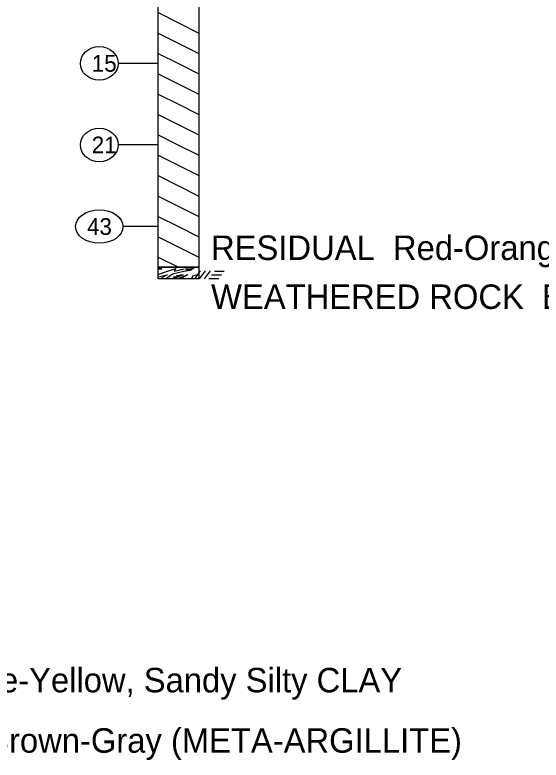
# Model space of a CAD drawing. Extents: x -26 to 303, y -74 to 518.
# Drawn here: x 158.98 to 191.22, y -74.2 to -28.53 of the extents above; entities that cross this region are included whole.
import ezdxf

# ---------------------------------------------------------------- set-up
doc = ezdxf.new("R2010")
doc.units = 0
for name, color, linetype in [('Prop Road Sect_ Boring - Material (Desc Tx)', 7, 'Continuous'), ('Prop Road Sect_ Boring - Material (Outline)', 7, 'Continuous'), ('Prop Road Sect_ Boring - Peripheral (HR Indicator)', 7, 'Continuous'), ('Prop Road Sect_ Boring - Peripheral (SPT Oval + Leader)', 7, 'Continuous'), ('Prop Road Sect_ Boring - Peripheral (SPT Tx)', 7, 'Continuous')]:
    doc.layers.add(name, color=color, linetype=linetype)

msp = doc.modelspace()

# ---------------------------------------------------------------- linework, layer by layer
at = {"layer": 'Prop Road Sect_ Boring - Material (Outline)'}
for p, q in [((167.75, -28.391), (168.999, -29.015)), ((167.75, -28.391), (168.999, -29.015)), ((168.999, -29.015), (170.248, -29.639)), ((168.999, -29.015), (170.248, -29.639)), ((167.75, -29.639), (170.248, -30.888)), ((167.75, -29.639), (170.248, -30.888)), ((167.75, -29.639), (170.248, -30.888)), ((167.75, -29.639), (170.248, -30.888)), ((170.248, -29.639), (170.25, -29.641)), ((170.248, -29.639), (170.25, -29.641)), ((170.248, -29.639), (170.25, -29.641)), ((170.248, -29.639), (170.25, -29.641)), ((167.75, -30.888), (168.999, -31.512)), ((167.75, -30.888), (168.999, -31.512)), ((170.248, -30.888), (170.25, -30.889)), ((170.248, -30.888), (170.25, -30.889)), ((168.999, -31.512), (170.248, -32.137)), ((168.999, -31.512), (170.248, -32.137)), ((167.75, -32.137), (170.248, -33.386)), ((167.75, -32.137), (170.248, -33.386)), ((167.75, -32.137), (170.248, -33.386)), ((167.75, -32.137), (170.248, -33.386)), ((170.248, -32.137), (170.25, -32.138)), ((170.248, -32.137), (170.25, -32.138)), ((170.248, -32.137), (170.25, -32.138)), ((170.248, -32.137), (170.25, -32.138)), ((167.75, -33.386), (168.999, -34.01)), ((167.75, -33.386), (168.999, -34.01)), ((170.248, -33.386), (170.25, -33.387)), ((170.248, -33.386), (170.25, -33.387)), ((168.999, -34.01), (170.248, -34.634)), ((168.999, -34.01), (170.248, -34.634)), ((167.75, -34.634), (170.248, -35.883)), ((167.75, -34.634), (170.248, -35.883)), ((167.75, -34.634), (170.248, -35.883)), ((167.75, -34.634), (170.248, -35.883)), ((170.248, -34.634), (170.25, -34.636)), ((170.248, -34.634), (170.25, -34.636)), ((170.248, -34.634), (170.25, -34.636)), ((170.248, -34.634), (170.25, -34.636)), ((167.75, -35.883), (168.999, -36.507)), ((167.75, -35.883), (168.999, -36.507)), ((170.248, -35.883), (170.25, -35.884)), ((170.248, -35.883), (170.25, -35.884)), ((168.999, -36.507), (170.248, -37.132)), ((168.999, -36.507), (170.248, -37.132)), ((167.75, -37.132), (170.248, -38.381)), ((167.75, -37.132), (170.248, -38.381)), ((167.75, -37.132), (170.248, -38.381)), ((167.75, -37.132), (170.248, -38.381)), ((170.248, -37.132), (170.25, -37.133)), ((170.248, -37.132), (170.25, -37.133)), ((170.248, -37.132), (170.25, -37.133)), ((170.248, -37.132), (170.25, -37.133)), ((167.75, -38.381), (168.999, -39.005)), ((167.75, -38.381), (168.999, -39.005)), ((170.248, -38.381), (170.25, -38.382)), ((170.248, -38.381), (170.25, -38.382)), ((168.999, -39.005), (170.248, -39.629)), ((168.999, -39.005), (170.248, -39.629)), ((167.75, -39.629), (170.248, -40.878)), ((167.75, -39.629), (170.248, -40.878)), ((167.75, -39.629), (170.248, -40.878)), ((167.75, -39.629), (170.248, -40.878)), ((170.248, -39.629), (170.25, -39.631)), ((170.248, -39.629), (170.25, -39.631)), ((170.248, -39.629), (170.25, -39.631)), ((170.248, -39.629), (170.25, -39.631)), ((167.75, -40.878), (168.999, -41.502)), ((167.75, -40.878), (168.999, -41.502)), ((170.248, -40.878), (170.25, -40.879)), ((170.248, -40.878), (170.25, -40.879)), ((168.999, -41.502), (170.248, -42.127)), ((168.999, -41.502), (170.248, -42.127)), ((167.75, -42.127), (170.248, -43.376)), ((167.75, -42.127), (170.248, -43.376)), ((167.75, -42.127), (170.248, -43.376)), ((167.75, -42.127), (170.248, -43.376)), ((170.248, -42.127), (170.25, -42.128)), ((170.248, -42.127), (170.25, -42.128)), ((170.248, -42.127), (170.25, -42.128)), ((170.248, -42.127), (170.25, -42.128)), ((167.75, -43.376), (168.999, -44)), ((167.75, -43.376), (168.999, -44)), ((170.248, -43.376), (170.25, -43.377)), ((170.248, -43.376), (170.25, -43.377)), ((167.789, -44.002), (168.014, -44.002)), ((167.789, -44.002), (168.014, -44.002)), ((167.789, -44.086), (167.989, -44.086)), ((167.789, -44.086), (167.989, -44.086)), ((169.414, -44.03), (169.814, -44.03)), ((169.414, -44.03), (169.814, -44.03)), ((169.464, -44.142), (169.739, -44.142)), ((169.464, -44.142), (169.739, -44.142)), ((167.75, -44.593), (168.318, -44.456)), ((167.75, -44.593), (168.318, -44.456)), ((168.318, -44.456), (167.889, -44.7)), ((168.318, -44.456), (167.889, -44.7)), ((169.289, -44.453), (168.649, -44.7)), ((169.289, -44.453), (168.649, -44.7)), ((168.688, -44.575), (168.974, -44.575)), ((168.688, -44.575), (168.974, -44.575)), ((168.873, -44.506), (169.152, -44.506)), ((168.873, -44.506), (169.152, -44.506)), ((169.585, -44.453), (168.944, -44.7)), ((169.585, -44.453), (168.944, -44.7)), ((169.089, -44.453), (169.289, -44.453)), ((169.089, -44.453), (169.289, -44.453)), ((169.585, -44.453), (169.107, -44.7)), ((169.585, -44.453), (169.107, -44.7)), ((170.248, -44.671), (170.134, -44.7)), ((170.248, -44.671), (170.134, -44.7)), ((170.248, -44.436), (170.25, -44.435)), ((170.248, -44.436), (170.25, -44.435)), ((170.248, -44.593), (170.25, -44.592)), ((170.248, -44.593), (170.25, -44.592))]:
    msp.add_line(p, q, dxfattribs=at)
for points in [[(167.75, -16), (170.25, -16), (170.25, -44), (167.75, -44)], [(167.75, -44), (170.25, -44), (170.25, -44.7), (167.75, -44.7)]]:
    msp.add_lwpolyline(points, close=True, dxfattribs=at)
for points in [[(167.75, -44.436), (168.018, -44.342), (168.396, -44.22), (168.843, -44.066), (168.788, -44.189), (168.745, -44.24), (169.342, -44.084)], [(167.75, -44.436), (168.018, -44.342), (168.396, -44.22), (168.843, -44.066), (168.788, -44.189), (168.745, -44.24), (169.342, -44.084)], [(168.21, -44.7), (168.639, -44.396), (169.339, -44.227), (169.714, -44.171), (170.001, -44)], [(168.21, -44.7), (168.639, -44.396), (169.339, -44.227), (169.714, -44.171), (170.001, -44)], [(170.248, -44.438), (170.189, -44.452), (169.864, -44.536), (169.798, -44.7)], [(170.248, -44.438), (170.189, -44.452), (169.864, -44.536), (169.798, -44.7)]]:
    msp.add_lwpolyline(points, dxfattribs=at)
at = {"layer": 'Prop Road Sect_ Boring - Peripheral (HR Indicator)'}
for p, q in [((170, -44.7), (170.361, -44.221)), ((170.3, -44.7), (170.661, -44.221)), ((170.6, -44.7), (170.961, -44.221)), ((171.205, -44.238), (171.805, -44.238)), ((170.869, -44.683), (171.469, -44.683)), ((171.037, -44.461), (171.637, -44.461))]:
    msp.add_line(p, q, dxfattribs=at)
at = {"layer": 'Prop Road Sect_ Boring - Peripheral (SPT Oval + Leader)'}
for p, q in [((167.75, -31.5), (165.31, -31.5)), ((167.75, -36.5), (165.31, -36.5)), ((167.75, -41.5), (165.601, -41.5))]:
    msp.add_line(p, q, dxfattribs=at)
for centre, major_axis, ratio in [((164.15, -31.5), (1.16, 0), 0.883591), ((164.15, -36.5), (1.16, 0), 0.883591), ((164.15, -41.5), (1.451, 0), 0.706609)]:
    msp.add_ellipse(centre, major_axis=major_axis, ratio=ratio, dxfattribs=at)

# ---------------------------------------------------------------- texts
at = {"layer": 'Prop Road Sect_ Boring - Material (Desc Tx)'}
for s, p in [('RESIDUAL  Red-Orange-Yellow, Sandy Silty CLAY', (171, -43.55)), ('WEATHERED ROCK  Brown-Gray (META-ARGILLITE)', (171, -46.55)), ('RESIDUAL  Red-Orange-Yellow, Sandy Silty CLAY', (137, -70.05)), ('WEATHERED ROCK  Brown-Gray (META-ARGILLITE)', (137, -73.75))]:
    msp.add_text(s, height=1.5, dxfattribs=at).set_placement(p)
at = {"layer": 'Prop Road Sect_ Boring - Peripheral (SPT Tx)'}
for s, p in [('15', (163.69, -32.012)), ('21', (163.69, -37.012)), ('43', (163.399, -42.012))]:
    msp.add_text(s, height=1.025, dxfattribs=at).set_placement(p)

doc.saveas('drawing.dxf')
